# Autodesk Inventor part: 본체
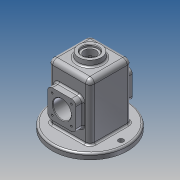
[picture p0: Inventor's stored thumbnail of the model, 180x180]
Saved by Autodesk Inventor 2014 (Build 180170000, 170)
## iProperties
Created: 2021-08
Part Number: 본체
Material: 알루미늄 6061
Document SubType Name: Modeling
Designer: kb542
Density: 2.71 g/cm^3
Appearance: 알루미늄 - 평지
Mass: 824.683 g
Surface Area: 947.808 cm^2
Volume: 304.311 cm^3
Author: kb542
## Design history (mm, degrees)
node "작업 평면1"
sketch "스케치1"
  geometry: L1 (0, 55)-(0, -55); C1 r 67 at (0, 0); C2 r 4.5 at (0, 55); C3 r 4.5 at (0, -55); A1 r 55 centre (0, 0) between (0, -55) and (0, 55); 2 further points
  constraints: 4 centre point, 4 coincident, 2 end point, 2 point on circle, 1 midpoint, 1 vertical
  dimensions: "d1" = 134 diameter of C1; "d2" = 110 diameter of A1; "d3" = 110 distance of L1.start L1.end; "d4" = 9 diameter of C2; "d5" = 9 diameter of C3
extrude "돌출1" new body sketch "스케치1" distance "d6" = 10; taper "d7" = 0 deg
sketch "스케치2"
  geometry: L1 (-37, -37)-(37, -37); L2 (37, -37)-(37, 37); L3 (37, 37)-(-37, 37); L4 (-37, 37)-(-37, -37); L5 (-37, -37)-(37, 37); L6 (37, -37)-(-37, 37); C1 r 67 at (0, 0) reference
  constraints: 12 end point, 2 midpoint, 2 parallel, 1 horizontal, 1 perpendicular
  dimensions: "d8" = 74 distance of L3.end L2.end; "d9" = 74 distance of L2.end L1.end
extrude "돌출2" join sketch "스케치2" distance "d10" = 100; taper "d11" = 0 deg
node "작업 평면2"
sketch "스케치3"
  geometry: C1 r 20 at (0, 0); 1 further point
  constraints: 1 centre point, 1 coincident
  dimensions: "d13" = 40 diameter of C1
extrude "돌출3" join sketch "스케치3" distance "d14" = 100; taper "d15" = 6 deg
sketch "스케치4"
  geometry: L1 (12, 20)-(62, 20); L2 (62, 20)-(62, 70); L3 (62, 70)-(12, 70); L4 (12, 70)-(12, 20); L5 (12, 20)-(62, 70); L6 (62, 20)-(12, 70); 2 further points
  constraints: 12 end point, 2 midpoint, 2 parallel, 1 coincident, 1 horizontal, 1 perpendicular
  dimensions: "d16" = 50 distance of L3.end L2.end; "d17" = 50 distance of L2.end L1.end
extrude "돌출4" join sketch "스케치4" distance "d18" = 13; taper "d19" = 0 deg
sketch "스케치5"
  geometry: C1 r 20 at (0, 0) reference; C2 r 14 at (0, 0)
  constraints: 1 centre point, 1 coincident
  dimensions: "d20" = 28 diameter of C2
extrude "돌출5" cut sketch "스케치5" distance "d21" = 4; taper "d22" = 0 deg
sketch "스케치6"
  geometry: C1 r 14 at (0, 0) reference; C2 r 10.5 at (0, 0)
  constraints: 1 centre point, 1 coincident
  dimensions: "d23" = 21 diameter of C2
extrude "돌출6" cut sketch "스케치6" distance "d24" = 60; taper "d25" = 0 deg
sketch "스케치7"
  geometry: L1 (-32, -32)-(32, -32); L2 (32, -32)-(32, 32); L3 (32, 32)-(-32, 32); L4 (-32, 32)-(-32, -32); L5 (-32, -32)-(32, 32); L6 (32, -32)-(-32, 32); C1 r 67 at (0, 0) reference
  constraints: 12 end point, 2 midpoint, 2 parallel, 1 horizontal, 1 perpendicular
  dimensions: "d26" = 64 distance of L3.end L2.end; "d27" = 64 distance of L2.end L1.end
extrude "돌출7" cut sketch "스케치7" distance "d28" = 105; taper "d29" = 0 deg
sketch "스케치8"
  geometry: C1 r 16 at (37, 45); 1 further point
  constraints: 1 centre point, 1 coincident
  dimensions: "d30" = 32 diameter of C1
extrude "돌출8" cut sketch "스케치8" distance "d31" = 105; taper "d32" = 0 deg
sketch "스케치9"
  geometry: L1 (-32, -55)-(-32, 50) reference; L2 (-32, 25)-(-25, 22.452); L3 (-25, 22.452)-(-25, 16); L4 (-25, 16)-(-32, 16); L5 (-50, 16)-(-32, 16) reference; L6 (-93.8, 0)-(93.8, 0) reference; 1 further point
  constraints: 6 end point, 2 point on line, 1 collinear, 1 parallel, 1 perpendicular
  dimensions: "d33" = 7 distance between parallel lines of L1 L3; "d34" = 110 deg angle of L1 L2; "d35" = 25 vertical distance of L2.start point (0, 0)
revolve "회전1" sketch "스케치9" stored, may be unused: angle "d36" = 90 deg
sketch "스케치10"
  geometry: L1 (20, 28)-(54, 28); L2 (54, 28)-(54, 62); L3 (54, 62)-(20, 62); L4 (20, 62)-(20, 28); L5 (20, 28)-(54, 62); L6 (54, 28)-(20, 62); C1 r 16 at (37, 45) reference; 4 further points
  constraints: 12 end point, 4 coincident, 2 midpoint, 2 parallel, 1 horizontal, 1 perpendicular
  dimensions: "d37" = 34 distance of L3.end L2.end; "d38" = 34 distance of L2.end L1.end
hole "구멍1" sketch "스케치10" at (20, 62), (20, 28), (54, 28), (54, 62) diameter "d39" = 3.242; stored, may be unused: countersink angle "d43" = 90 deg, drill point angle "d45" = 118 deg; dims "d40" = 8, "d41" = 4, "d42" = 2, "d44" = 10
fillet "모깎기1" dims "d46" = 8
chamfer "모따기1" distance "d47" = 1; stored, may be unused: second distance "d48" = 2, angle "d49" = 45 deg
fillet "모깎기2" dims "d50" = 3
sketch "스케치11"
  geometry: L1 (9, 18)-(49, 18) reference; 2 further points
  constraints: 1 vertical alignment, 1 other
  dimensions: "d51" = 28 distance from line of L1 point (29, -10)
feature "엠보싱1" sketch "스케치11" dims "d1" = 134, "d2" = 110, "d3" = 110, "d4" = 9, "d5" = 9, "d52" = 0.5, "d53" = 0
node "솔리드1"
mirror "대칭1"
mirror "대칭2"
mirror "대칭3"
other parameters: "d0" = -55
